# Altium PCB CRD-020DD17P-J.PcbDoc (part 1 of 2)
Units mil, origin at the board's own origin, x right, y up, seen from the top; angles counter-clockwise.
Board outline 2331 x 1574.8 mil, 4 copper layers (TOP, GND02, PWR03, BOTTOM), stack 63 mil thick; 83 components, 45 nets, 202 pads, 150 vias.
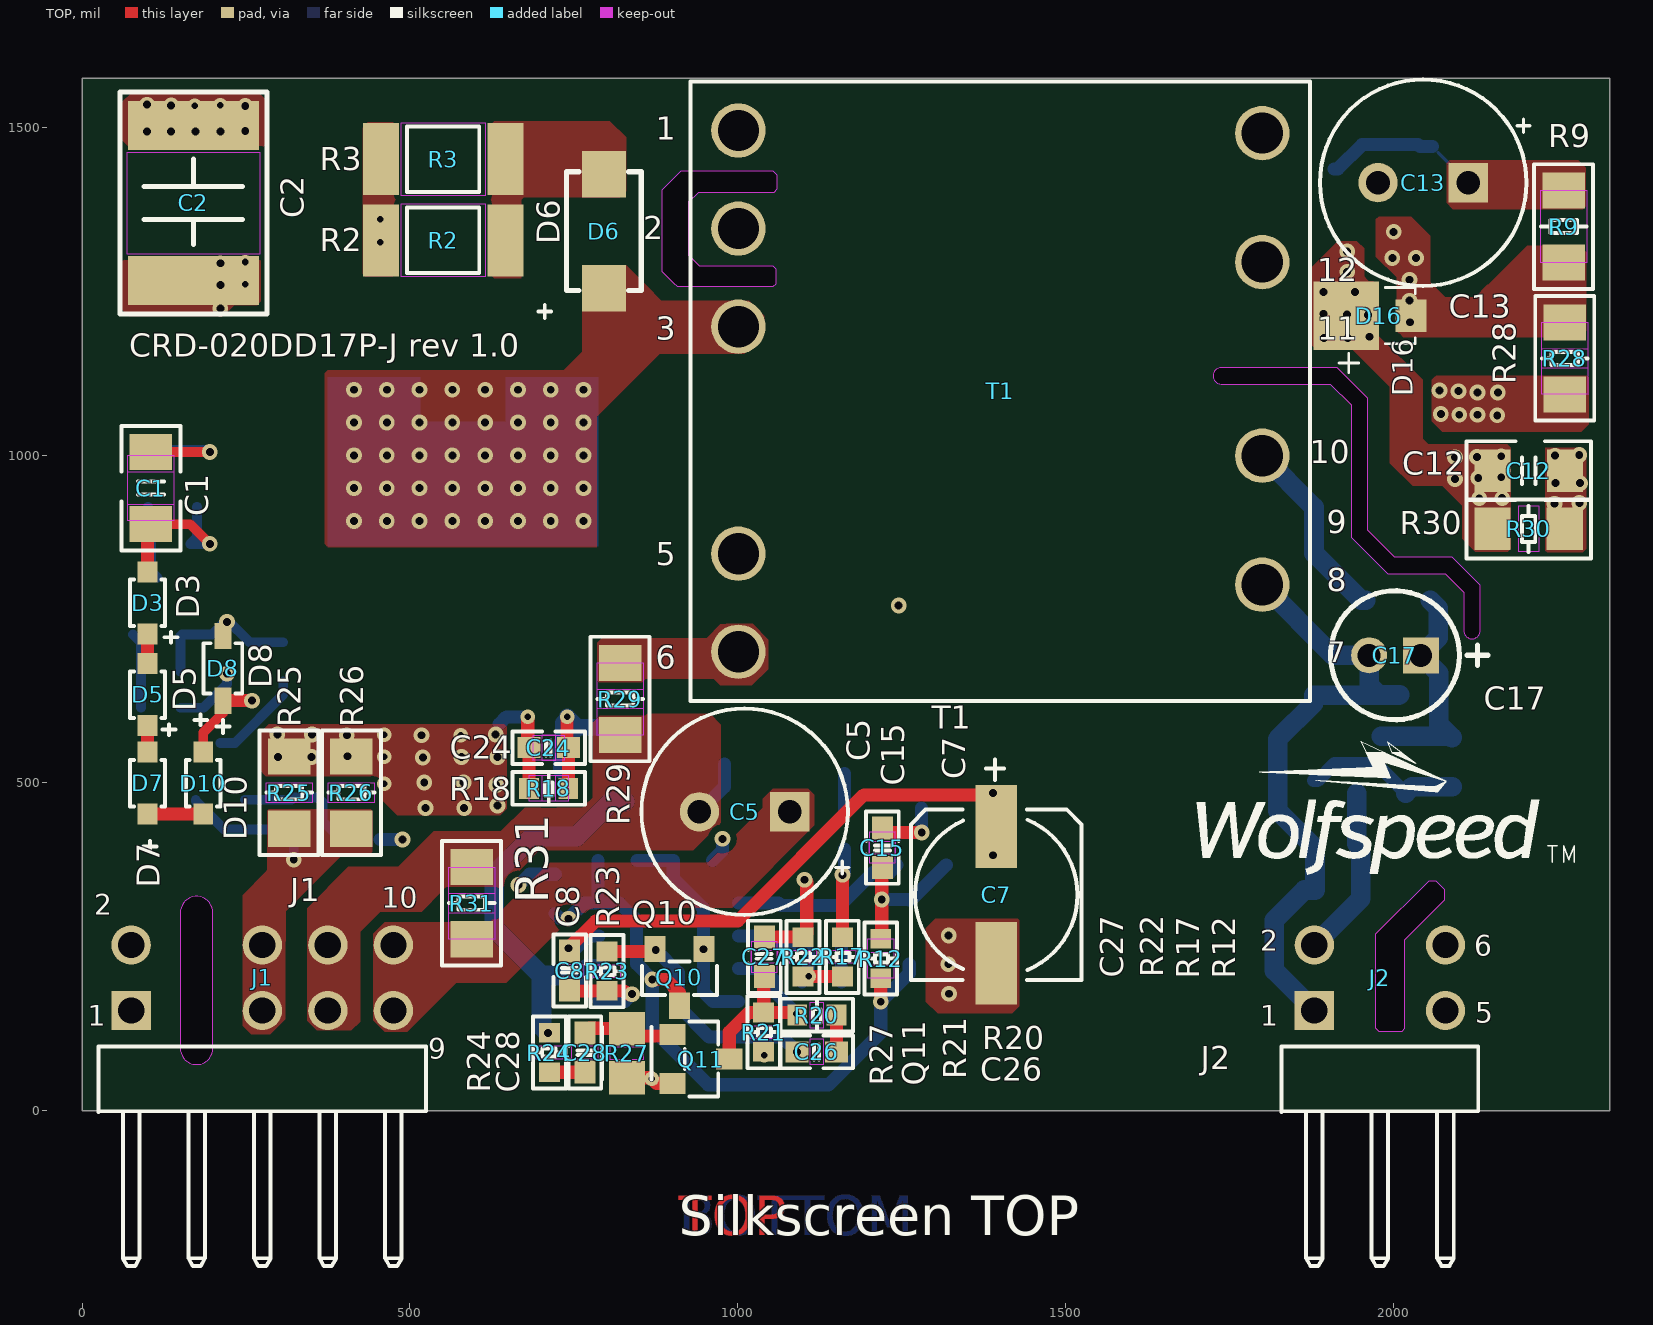
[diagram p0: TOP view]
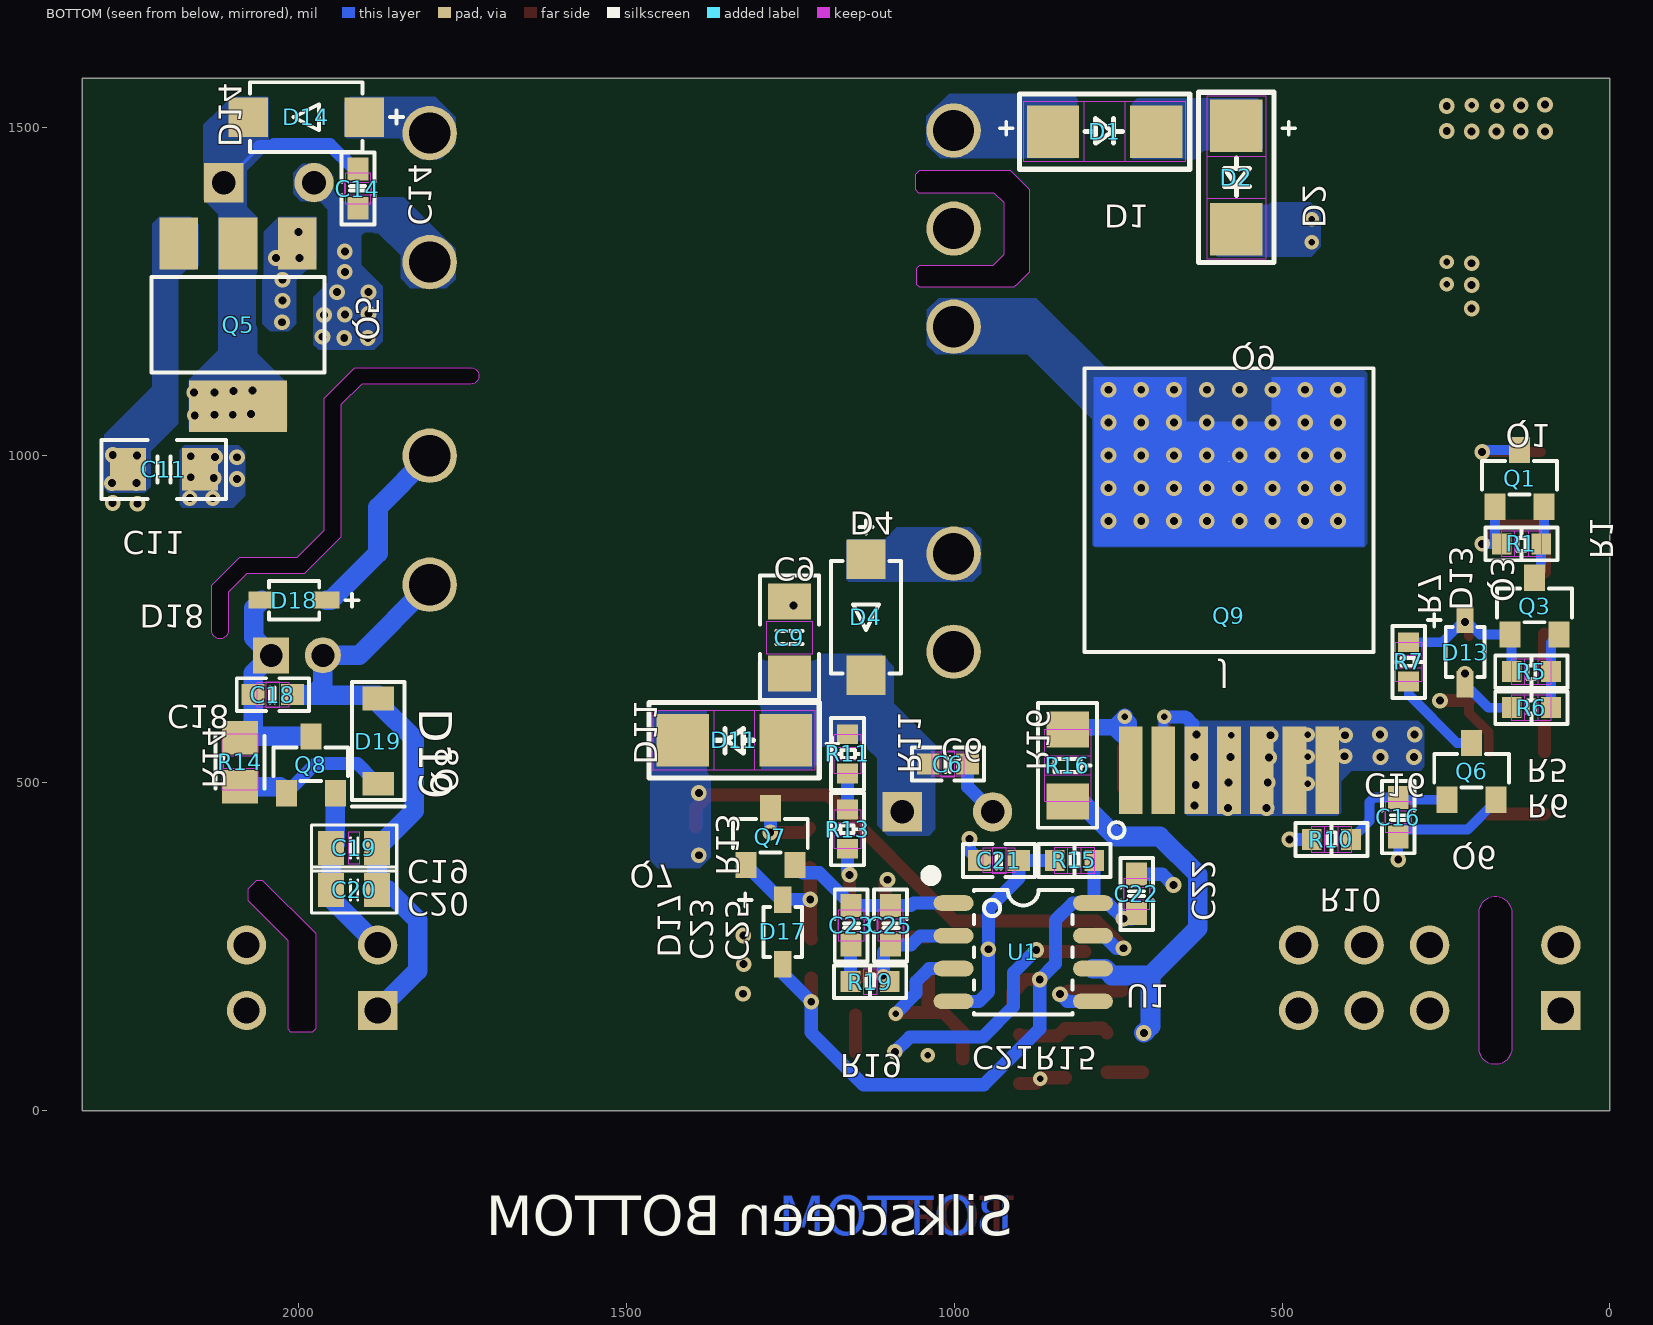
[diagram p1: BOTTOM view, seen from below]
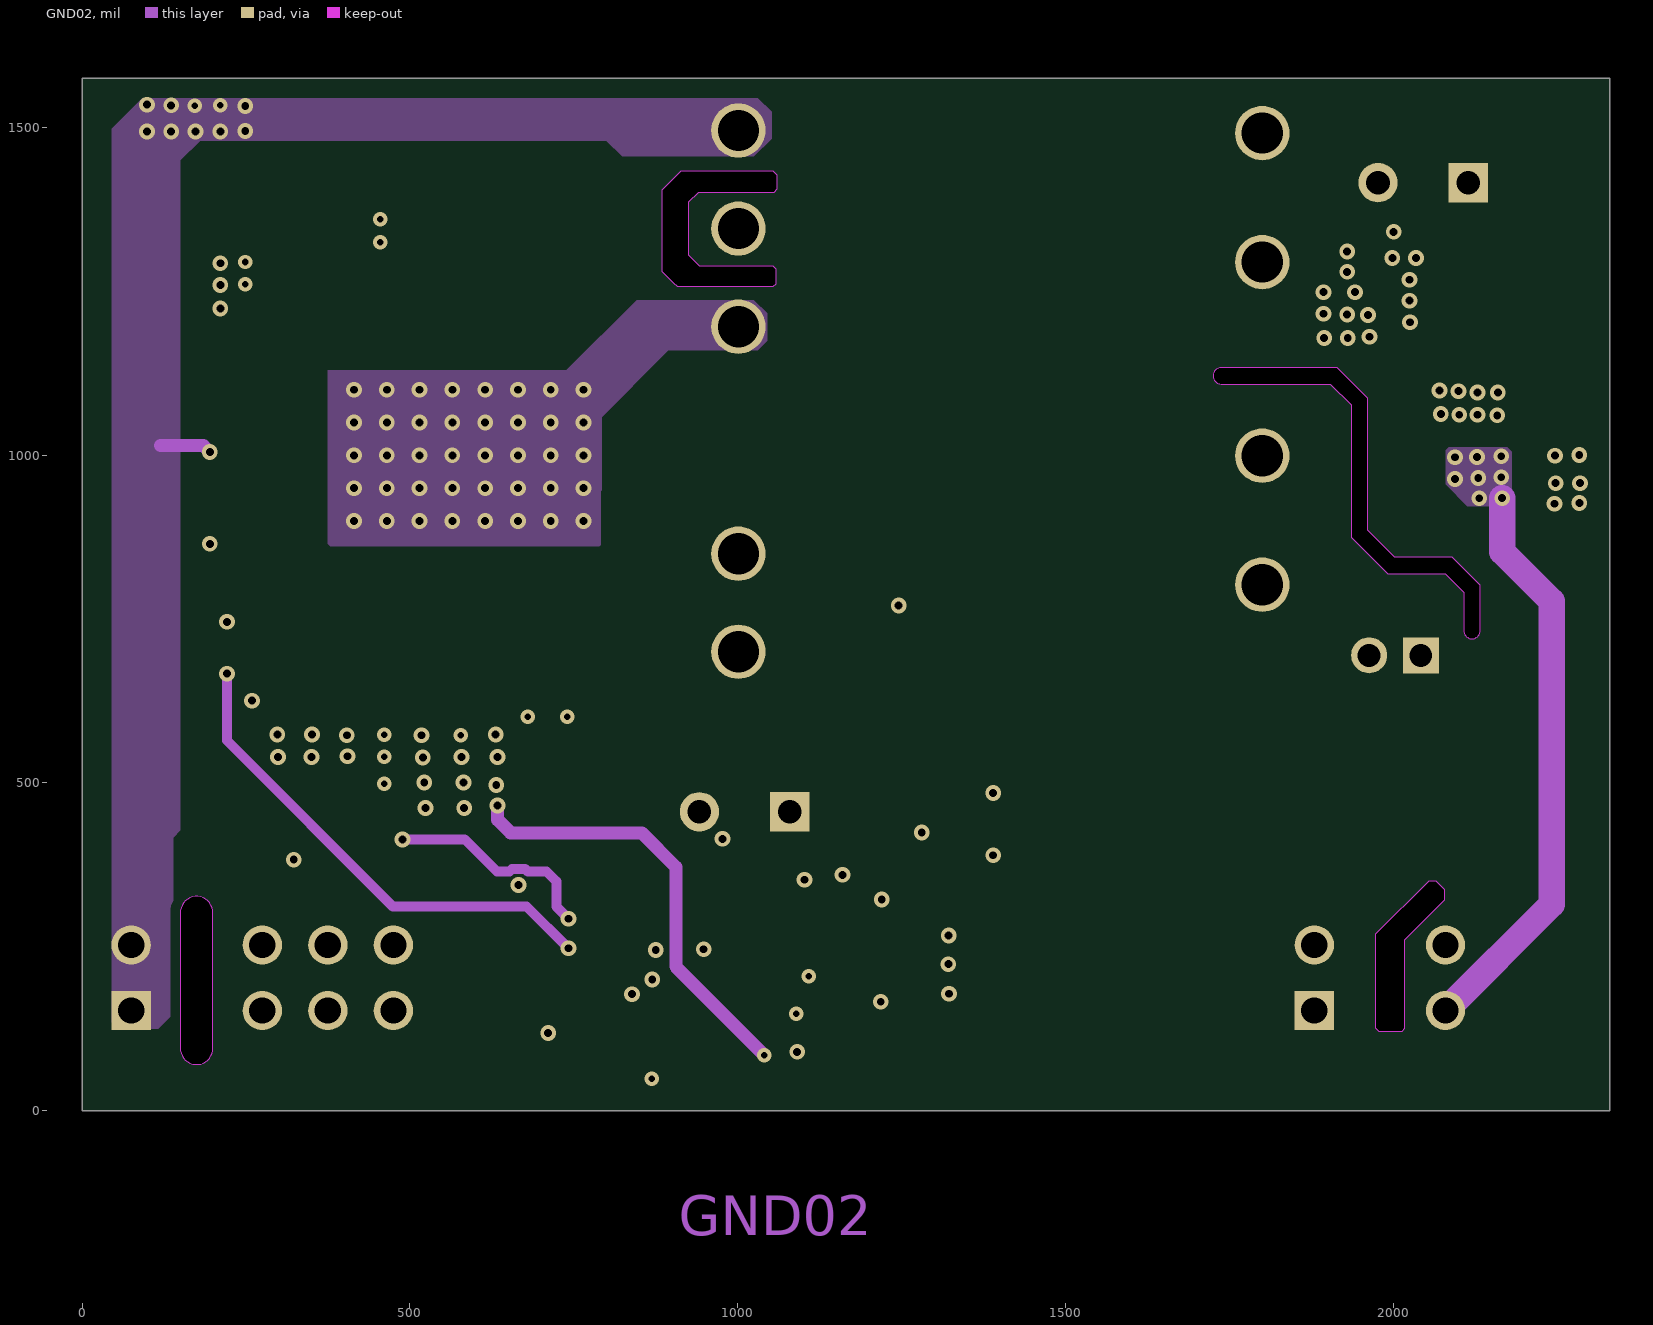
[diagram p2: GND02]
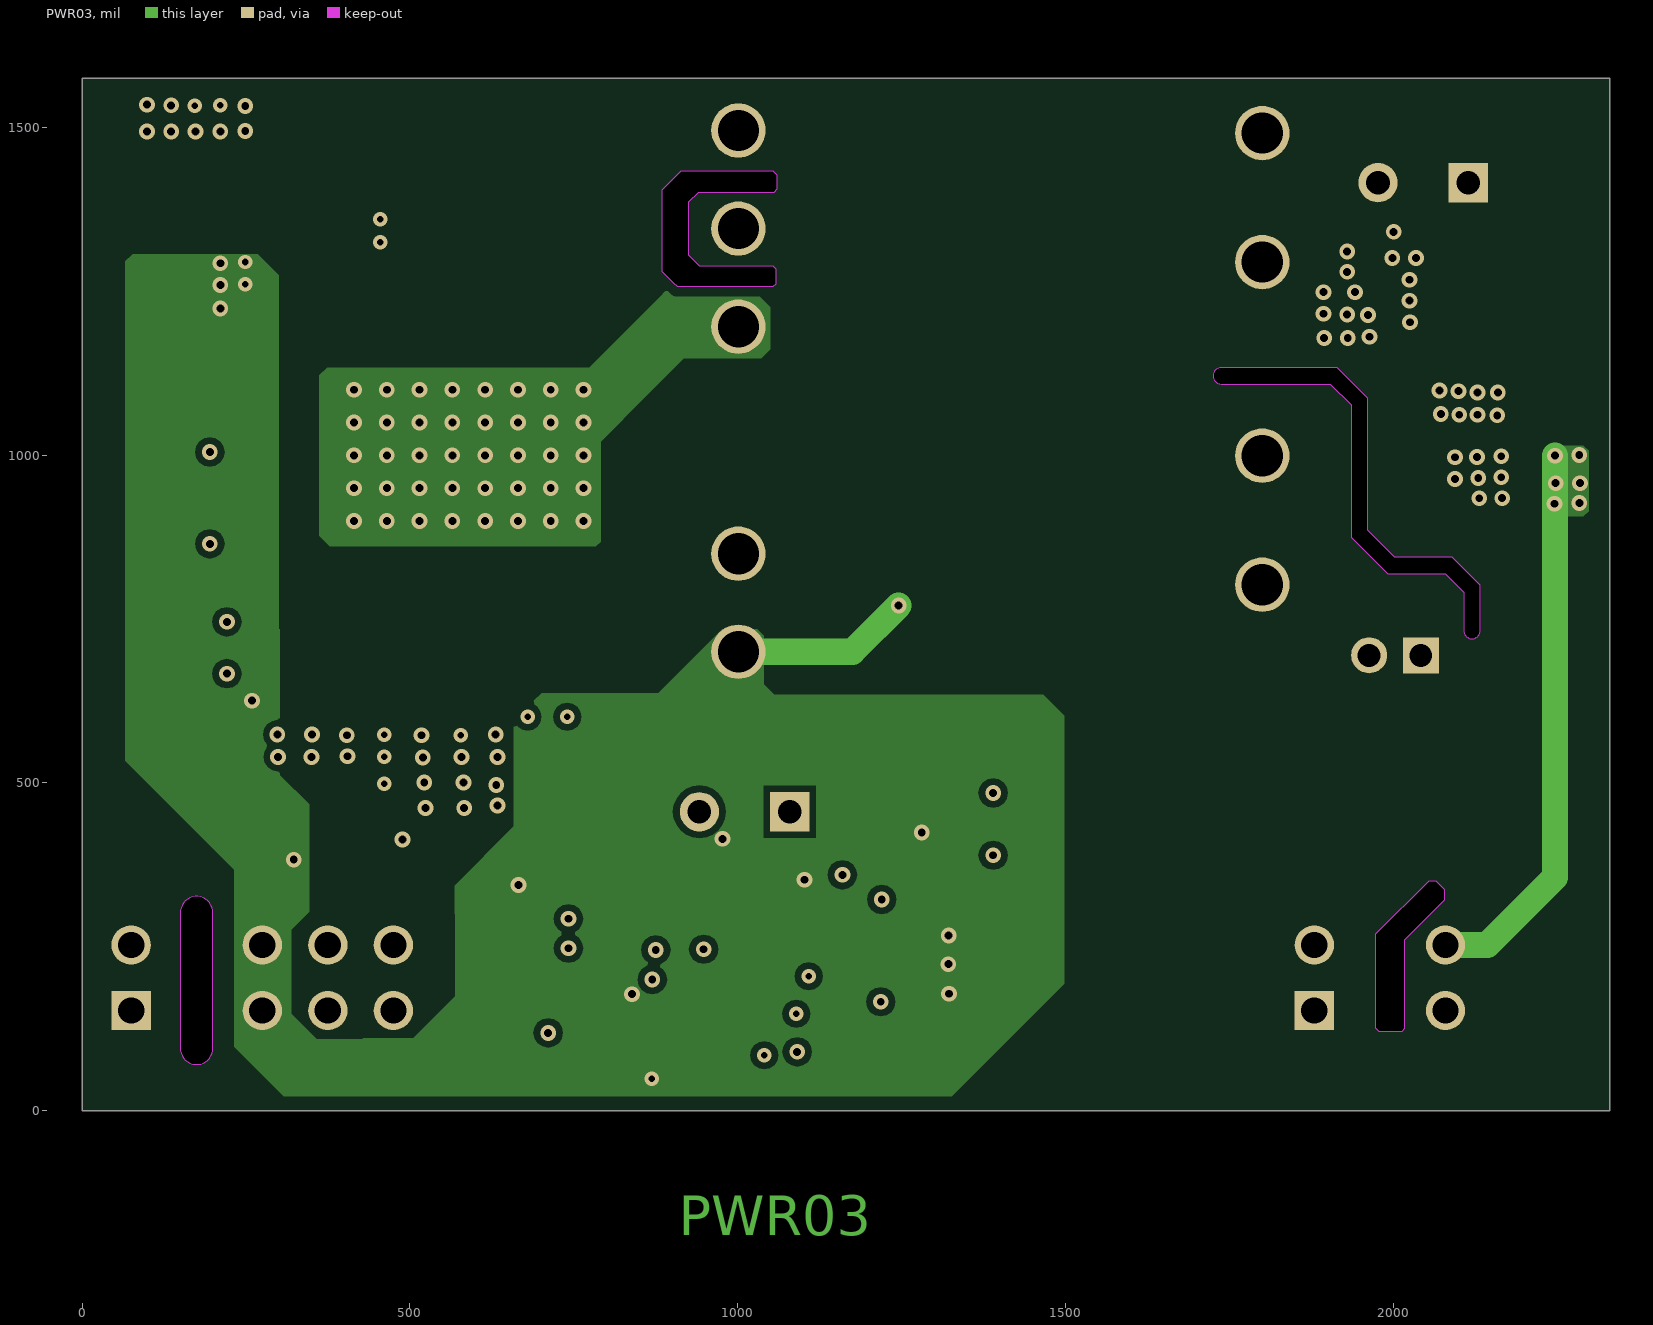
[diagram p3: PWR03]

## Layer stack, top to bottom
Top Solder: solder mask 0.4, Solder Resist, Dk 3.5
TOP: signal copper 1.4
Dielectric 1: core 8.5, FR-4, Dk 4.5
GND02: signal copper 1.2
Dielectric2: core 40.8, FR-4, Dk 4.5
PWR03: signal copper 1.2
Dielectric3: core 8.5, FR-4, Dk 4.5
BOTTOM: signal copper 1.4
Bottom Solder: solder mask 0.4, Solder Resist, Dk 3.5

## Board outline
40,0 0,0 0,1574.8 40,1574.8 2246,1574.8 2331,1574.8 2331,0 2246,0
cut-out: 1737.91,1108.63 1904.29,1108.63 1936.22,1076.71 1936.22,875.2 1992.32,819.09 2079.84,819.09 2108,790.94 2108,732.44 ccw(c2120.5,732.44) 2133,732.44 2133,801.29 2090.2,844.09 2002.68,844.09 1961.22,885.55 1961.22,1087.06 1914.65,1133.63 1737.91,1133.63 ccw(c1737.91,1121.13)
cut-out: 149.74,301.9 149.74,95.45 ccw(c174.74,95.45) 199.74,95.45 199.74,301.9 ccw(c174.74,301.9)
cut-out: 940,1400.8 925,1385.8 925,1319.8 925,1305.8 938,1292.8 942,1288.8 1054,1288.8 1058,1284.8 1058,1264.8 1058,1260.8 1054,1256.8 908.5,1256.8 902.5,1262.3 885,1279.8 885,1404.8 914,1433.8 940,1433.8 1032,1433.8 1054,1433.8 1060,1427.8 1060,1405.8 1055,1400.8 1035,1400.8 1025,1400.8 945,1400.8
cut-out: 2055,350.8 2065,350.8 2078,337.8 2078,320.8 2017,259.8 2017,124.8 2013,120.8 1979,120.8 1974,125.8 1974,269.8

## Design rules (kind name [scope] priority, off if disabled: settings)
BoardOutlineClearance [All] p1: gap=10 ignorepadtopadclearanceinfootprint=FALSE
Clearance [All] p1: gap=5 ignorepadtopadclearanceinfootprint=FALSE
MinimumSolderMaskSliver [All] p1: minsoldermaskwidth=4
PlaneConnect [All] p1: planeconnectstyle=Direct reliefexpansion=20 reliefentries=4 reliefconductorwidth=10 reliefairgap=10
PolygonConnect [All] p1: connectstyle=Direct reliefconductorwidth=10 reliefentries=4 polygonreliefangle="90 Angle" airgapwidth=10
RoutingVias [All] p1: holewidth=28 width=50 viastyle="Through Hole" minholewidth=28 minwidth=50 maxholewidth=28 maxwidth=50
SilkToSilkClearance [All] p1: silktosilkclearance=5
SilkToSolderMaskClearance [IsPad] p1: minsilkscreentomaskgap=5 clearancetoexposedcopper=TRUE
SolderMaskExpansion [All] p1: expansion=4 istentingtop=FALSE
SupplyNets "Schematic Supply Nets_6" [InNet('S_15V')] p1: voltage=0.000
SupplyNets "Schematic Supply Nets_5" [InNet('SGND')] p2: voltage=0.000
SupplyNets "Schematic Supply Nets_4" [InNet('CAN_GND')] p3: voltage=0.000
SupplyNets "Schematic Supply Nets_3" [InNet('CAN+5V')] p4: voltage=0.000
SupplyNets "Schematic Supply Nets_2" [InNet('PGND')] p5: voltage=0.000
SupplyNets "Schematic Supply Nets_1" [InNet('AGND')] p6: voltage=0.000
SupplyNets "Schematic Supply Nets" [InNet('P_15V')] p7: voltage=0.000
Width [All] p1: maxlimit=100 minlimit=5 preferedwidth=8
26 further rules are at their usual default settings.

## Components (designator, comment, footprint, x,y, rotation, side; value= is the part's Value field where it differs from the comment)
C1 "1.5pF" C1206#1 105,949.8 r270 top
C2 "0.22UF" C2220 170,1384.8 r270 top
C5 "APSG250ELL181MH08S" C7C9C13-RNU1E221MDNASQ 1010.78,456.08 r180 top
C6 "1U" C0603#1 1010,528.94 r180 bottom
C7 "35TZV22M6.3X6.1" CAP6_6X6_6 1394.65,329.31 r270 top
C8 "1U" C0603#2 744,213.8 r270 top
C9 "4.7uF" C1206#2 1251.74,721.69 r270 bottom
C11 "10uF" C1206#3 2206.12,978.36 r180 bottom
C12 "10uF" C1206#3 2207.12,976.36 r180 top
C13 "APSG250ELL181MH08S" C7C9C13-RNU1E221MDNASQ 2046,1415.8 r180 top
C14 "1U" C0603#3 1910,1406.8 r90 bottom
C15 "0.33u" 0603#1 1220.96,401.3 r90 top value=0.1uF
C16 "47n" 0603#2 323,447.8 r270 bottom value=0.1uF
C17 "16SEPG150M" C17_16SEPG150M 2003,694.8 r180 top
C18 "1U" C0603#1 2040,634.8 r180 bottom
C19 "10u" C0805#1 1916,400.8 r0 bottom
C20 "10u" C0805#2 1916,336.8 r0 bottom
C21 "1n" C0603#1 932,381.8 r180 bottom
C22 "0.1u" C0603#3 722,330.8 r90 bottom
C23 "22n" 0603#2 1157.62,282.79 r270 bottom value=0.1uF
C24 "1n" C0603#1 712,553.8 r0 top
C25 "100p" C0603#3 1097.62,282.79 r270 bottom
C26 "2.2u" 0603#3 1121,89.8 r0 top
C27 "100p" C0603#1 1041,234.8 r270 top
C28 "22p" C0603#2 767.12,88.74 r90 top
D1 "SMAJ300CA" SMA#1 771,1493.8 r0 bottom
D2 "SMAJ300CA" SMA#2 570,1423.8 r270 bottom
D3 "130V" SOD-323F 100,774.8 r90 top
D4 "SK5150AFL-TP" DO221AC#1 1135,752.8 r90 bottom
D5 "130V" SOD-323F 100,634.8 r90 top
D6 "BYG10YHE3_A/I" DO214AC 796,1341.8 r90 top
D7 "130V" SOD-323F 100,499.8 r90 top
D8 "22V" SOD323#1 215,674.8 r90 top
D10 "130V" SOD-323F 185,499.8 r270 top
D11 "SS16HE3_B/H" SMA#1 1336.11,565.25 r180 bottom
D13 "18V" SOD323#2 221,699.8 r90 bottom
D14 "SK5150AFL-TP" DO221AC#2 1989,1515.8 r0 bottom
D16 "15.6V" DO220AA 1965,1212.8 r0 top
D17 "SD101CWS-HE3-08" SOD323#2 1262.02,272.68 r90 bottom
D18 "BAS100CS_R1_00001" SOD323#1 2007.56,778.82 r0 bottom
D19 "5.6V" SMDSOD123 1879,563.8 r90 bottom
J1 "Connector6" HPR2X4H-254MM-80 275,25.42 r0 top
J2 "Connector6" HPR2X3H-254MM-90 1980,25.42 r0 top
Q1 "TO247-3" SOT23-3 138.01,964.8 r180 bottom
Q3 "TO247-3" SOT23-3 115.01,769.8 r180 bottom
Q5 "PBSS306NZ,135" SOT223 2093,1198.8 r0 bottom
Q6 "" TO236AB 211,517.8 r180 bottom
Q7 "PMBT2907A,235" TO236AB 1280.98,418.27 r180 bottom
Q8 "FMMTL619TA" SOT23-3 1982,527.8 r180 bottom
Q9 "J" D2PAK7L 580.87,915.43 r180 bottom
Q10 "MMBT3904,215" TO-236AB 911.33,203.3 r180 top
Q11 "MMBT3904,215" TO-236AB 944.07,78.82 r270 top
R1 "1M" R0603#1 135,863.8 r0 bottom
R2 "61.9R" R2010 551,1327.8 r0 top
R3 "61.9R" R2010 551,1451.8 r0 top
R5 "1M" R0603#1 120,668.8 r0 bottom
R6 "1k" R0603#1 120,615.8 r180 bottom
R7 "10k" R0603#2 308,684.8 r270 bottom
R9 "510R" R1206#1 2261.43,1348.89 r90 top
R10 "10k" R0603#1 425,414.8 r180 bottom
R11 "0" R0603#2 1162.08,544.43 r90 bottom
R12 "20k" R0603#1 1219.53,232.11 r270 top
R13 "2.49k" R0603#2 1164.08,429.43 r270 bottom
R14 "1k" R0805#1 2090,531.8 r270 bottom
R15 "40.2k" R0603#1 817,382.8 r180 bottom
R16 "10R" 1206 826.49,526.7 r270 bottom
R17 "15k" R0603#3 1161,234.8 r270 top
R18 "10k" R0603#1 712,490.8 r180 top
R19 "324k" R0603#3 1128.62,197.79 r180 bottom
R20 "4.02k" R0603#3 1121,144.8 r180 top
R21 "1k" R0603#3 1041,119.8 r270 top
R22 "3.3k" R0603#3 1101,234.8 r270 top
R23 "15k" R0603#3 802,212.8 r270 top
R24 "2k" R0603#3 712.12,88.74 r90 top
R25 "1.8R" R1206#2 315,485.14 r270 top
R26 "1.8R" R1206#2 410,485.14 r270 top
R27 "127" R0805#2 831.07,87.82 r270 top
R28 "510R" R1206#3 2261.03,1147.81 r270 top
R29 "0" R1206#3 822.03,628.1 r90 top
R30 "50K" R1206#2 2206.99,886.57 r0 top
R31 "50K" R1206#3 593.42,316.6 r270 top
T1 "750345357" XFMRS9_380-2400X2400_750345357 1401,1097.8 r0 top
U1 "UCC28C58QDRQ1" SOIC-8 895,241.8 r180 bottom

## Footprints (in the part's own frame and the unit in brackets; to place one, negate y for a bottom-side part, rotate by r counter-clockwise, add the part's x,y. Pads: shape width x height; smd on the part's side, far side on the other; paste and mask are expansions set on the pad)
0603#1 [mil] "0603"
  rect 35x32 smd: 1(-30,0) 2(30,0)
  TOP keep-out region: -24,-19 -24,19 24,19 24,-19
  TOP keep-out region: -10,-20 -10,20 10,20 10,-20
  silkscreen extent -55,-25 55,25, body extent -55,-25 55,25, height 150
0603#2 [mil] "0603"
  rect 35x32 smd: 1(30,0) 2(-30,0)
  TOP keep-out region: 24,19 24,-19 -24,-19 -24,19
  TOP keep-out region: 10,20 10,-20 -10,-20 -10,20
  silkscreen extent -55,-25 55,25, body extent -55,-25 55,25, height 150
0603#3 [mil] "0603"
  rect 35x32 smd: 1(-30,0) 2(30,0)
  TOP keep-out region: -10,-20 -10,20 10,20 10,-20
  silkscreen extent -55,-25 55,25, body extent -55,-25 55,25, height 150
1206 [mil] "1206"
  rect 55x65 smd: 1(55,-1) 2(-55,-1)
  TOP keep-out region: 15,-36 -15,-36 -15,34 15,34
  TOP keep-out region: 55,-36 -55,-36 -55,34 55,34
  silkscreen extent -95,-46 95,44, body extent -98,-46 98,46, height 150
C7C9C13-RNU1E221MDNASQ [mil] "C7C9C13-RNU1E221MDNASQ"
  rect 60x60 hole 36: 1(-68.9,0)
  round 60 hole 36: 2(68.9,0)
  silkscreen extent -159,-157 157,157, body extent -168,-168 168,168, height 150
C17_16SEPG150M [mil] "C17_16SEPG150M"
  rect 55x55 hole 35: 1(-39.37,0)
  round 55 hole 35: 2(39.37,0)
  silkscreen extent -142,-110 110,110, body extent -99,-99 99,99, height 150
C0603#1 [mil] "C0603"
  rect 35x32 smd: 1(-30,0) 2(30,0)
  TOP keep-out region: -24,-19 -24,19 24,19 24,-19
  TOP keep-out region: -10,-20 -10,20 10,20 10,-20
  silkscreen extent -55,-25 55,25, body extent -55,-25 55,25, height 150
C0603#2 [mil] "C0603"
  rect 35x32 smd: 1(-30,0) 2(30,0)
  TOP keep-out region: -10,-20 -10,20 10,20 10,-20
  silkscreen extent -55,-25 55,25, body extent -55,-25 55,25, height 150
C0603#3 [mil] "C0603"
  rect 35x32 smd: 1(30,0) 2(-30,0)
  TOP keep-out region: 24,19 24,-19 -24,-19 -24,19
  TOP keep-out region: 10,20 10,-20 -10,-20 -10,20
  silkscreen extent -55,-25 55,25, body extent -55,-25 55,25, height 150
C0805#1 [mil] "C0805"
  rect 40x52 smd: 1(-35,0) 2(35,0)
  TOP keep-out region: 8,25 8,-25 -8,-25 -8,25
  silkscreen extent -65,-35 65,35, body extent -65,-35 65,35, height 150
C0805#2 [mil] "C0805"
  rect 40x52 smd: 1(-35,0) 2(35,0)
  silkscreen extent -65,-35 65,35, body extent -65,-35 65,35, height 150
C1206#1 [mil] "C1206"
  rect 55x65 smd: 1(-55,0) 2(55,0)
  TOP keep-out region: -50,-35 -50,35 50,35 50,-35
  TOP keep-out region: -25,-35 -25,35 25,35 25,-35
  silkscreen extent -95,-45 95,45, body extent -95,-45 95,45, height 150
C1206#2 [mil] "C1206"
  rect 55x65 smd: 1(55,0) 2(-55,0)
  TOP keep-out region: 25,35 25,-35 -25,-35 -25,35
  silkscreen extent -95,-45 95,45, body extent -95,-45 95,45, height 150
C1206#3 [mil] "C1206"
  rect 55x65 smd: 1(-55,0) 2(55,0)
  silkscreen extent -95,-45 95,45, body extent -95,-45 95,45, height 150
C2220 [mm] "C2220"
  rect 1.905x5.08 smd: 1(-3,0) 2(3,0)
  TOP keep-out region: -1.95,2.59 -1.95,-2.59 1.96,-2.59 1.96,2.59
  silkscreen extent -4.3,-2.85 4.3,2.85, body extent -2.8,-2.5 2.8,2.5, height 3.81
CAP6_6X6_6 [mil] "CAP6_6X6_6"
  rect 126x63 smd: 1(-104.33,0) 2(104.33,0)
  silkscreen extent -207,-130 130,130, body extent -130,-130 130,130, height 150
D2PAK7L [mil] "D2PAK7L"
  rect 36x134 smd: 1(-150.39,-396.04) 2(-100.39,-396.04) 3(-50.39,-396.04) 4(-0.39,-396.04) 5(49.61,-396.04) 6(99.61,-396.04) 7(149.61,-396.04)
  round 1 smd: 8(-0.39,74.79)
  TOP region: 64.57,203.49 64.57,135.85 -65.35,135.85 -65.35,203.49 -206.69,203.49 -206.69,-53.91 205.91,-53.91 205.91,203.49
  silkscreen extent -221,-499 220,217, body extent -220,-215 220,215, height 150
DO214AC [mil] "DO214AC"
  rect 71x67 smd: 1(-87.21,0) 2(87.21,0)
  silkscreen extent -132,-57 91,100, body extent -126,-58 126,58, height 150
DO220AA [mil] "DO220AA"
  rect 100x105 smd: 1(-36,0)
  rect 47x50 smd: 2(62.5,0)
  silkscreen extent -47,-87 69,43
DO221AC#1 [mil] "DO221AC"
  rect 60x60 smd: 1(88.58,0) 2(-88.58,0)
  silkscreen extent -86,-53 148,53, body extent -122,-54 122,54, height 150
DO221AC#2 [mil] "DO221AC"
  rect 60x60 smd: 1(-88.58,0) 2(88.58,0)
  silkscreen extent -148,-53 86,53, body extent -122,-54 122,54, height 150
HPR2X3H-254MM-90 [mil] "HPR2X3H-254MM-90"
  rect 60x60 hole 40: 1(-100,127.38)
  round 60 hole 40: 2(-100,227.38) 5(100,127.38) 6(100,227.38)
  silkscreen extent -150,-262 150,72
HPR2X4H-254MM-80 [mil] "HPR2X4H-254MM-80"
  rect 60x60 hole 40: 1(-200,127.38)
  round 60 hole 40: 2(-200,227.38) 5(0,127.38) 6(0,227.38) 7(100,127.38) 8(100,227.38) 9(200,127.38) 10(200,227.38)
  silkscreen extent -250,-262 250,72
R0603#1 [mil] "R0603"
  rect 30x32 smd: 1(-30,-1) 2(30,-1)
  TOP keep-out region: -10,19 10,19 10,-21 -10,-21
  TOP keep-out region: -30,19 30,19 30,-21 -30,-21
  silkscreen extent -55,-26 55,24, body extent -56,-26 56,26, height 150
R0603#2 [mil] "R0603"
  rect 30x32 smd: 1(30,1) 2(-30,1)
  TOP keep-out region: 10,-19 -10,-19 -10,21 10,21
  TOP keep-out region: 30,-19 -30,-19 -30,21 30,21
  silkscreen extent -55,-24 55,26, body extent -56,-26 56,26, height 150
R0603#3 [mil] "R0603"
  rect 30x32 smd: 1(-30,-1) 2(30,-1)
  TOP keep-out region: -10,19 10,19 10,-21 -10,-21
  silkscreen extent -55,-26 55,24, body extent -56,-26 56,26, height 150
R0805#1 [mil] "R0805"
  rect 51x55 smd: 1(37.5,0) 2(-37.5,0)
  TOP keep-out region: 42.5,27.5 -42.5,27.5 -42.5,-27.5 42.5,-27.5
  TOP keep-out region: 10,-25 -10,-25 -10,25 10,25
  silkscreen extent -40,-38 40,38, body extent -63,-28 63,28, height 150
R0805#2 [mil] "R0805"
  rect 51x55 smd: 1(-37.5,0) 2(37.5,0)
  TOP keep-out region: -10,25 10,25 10,-25 -10,-25
  silkscreen extent -40,-38 40,38, body extent -63,-28 63,28, height 150
R1206#1 [mil] "R1206"
  rect 55x65 smd: 1(-55,1) 2(55,1)
  TOP keep-out region: -55,36 55,36 55,-34 -55,-34
  silkscreen extent -95,-44 95,46, body extent -98,-46 98,46, height 150
R1206#2 [mil] "R1206"
  rect 55x65 smd: 1(-55,1) 2(55,1)
  TOP keep-out region: -15,36 15,36 15,-34 -15,-34
  silkscreen extent -95,-44 95,46, body extent -98,-46 98,46, height 150
R1206#3 [mil] "R1206"
  rect 55x65 smd: 1(-55,1) 2(55,1)
  TOP keep-out region: -15,36 15,36 15,-34 -15,-34
  TOP keep-out region: -55,36 55,36 55,-34 -55,-34
  silkscreen extent -95,-44 95,46, body extent -98,-46 98,46, height 150
R2010 [mil] "R2010"
  rect 55x110 smd: 1(-95,0) 2(95,0)
  TOP keep-out region: -65,-55 65,-55 65,55 -65,55
  TOP keep-out region: 65,55 -65,55 -65,-55 65,-55
  silkscreen extent -55,-50 55,50, body extent -122,-55 122,55, height 150
SMA#1 [mil] "SMA"
  rect 80x80 smd: 1(78.74,0) 2(-78.74,0)
  TOP keep-out region: -31.5,45.28 -31.5,-45.28 31.5,-45.28 31.5,45.28
  TOP keep-out region: -124.02,45.28 -124.02,-45.28 124.02,-45.28 124.02,45.28
  silkscreen extent -130,-57 160,57, body extent -110,-57 110,57, height 150
SMA#2 [mil] "SMA"
  rect 80x80 smd: 1(-78.74,0) 2(78.74,0)
  TOP keep-out region: 31.5,-45.28 31.5,45.28 -31.5,45.28 -31.5,-45.28
  TOP keep-out region: 124.02,-45.28 124.02,45.28 -124.02,45.28 -124.02,-45.28
  silkscreen extent -130,-57 130,90, body extent -110,-57 110,57, height 150
SMDSOD123 [mil] "SMDSOD123"
  rect 36x48 smd: 1(65,0) 2(-65,0)
  silkscreen extent -100,-40 90,40, body extent -76,-34 76,33, height 56
SOD323#1 [mil] "SOD323"
  rect 40x26 smd: 1(-49.21,0) 2(49.21,0)
  silkscreen extent -98,-30 38,30, body extent -72,-31 72,31, height 150
SOD323#2 [mil] "SOD323"
  rect 40x26 smd: 1(49.21,0) 2(-49.21,0)
  silkscreen extent -38,-30 58,57, body extent -72,-31 72,31, height 150
SOD-323F [mil] "SOD-323F"
  rect 32x30 smd: 1(-47.24,0) 2(47.24,0)
  silkscreen extent -60,-46 35,27, body extent -53,-27 53,27, height 150
SOIC-8 [mil] "SOIC-8"
  oval 61x24 smd: 1(-106.3,75) 2(-106.3,25) 3(-106.3,-25) 4(-106.3,-75) 5(106.3,-75) 6(106.3,-25) 7(106.3,25) 8(106.3,75)
  silkscreen extent -149,-95 75,125, body extent -140,-95 140,95, height 150
SOT23-3 [mil] "SOT23-3"
  rect 32x40 smd: B(-37.39,-43.31) C(0.01,43.31) E(37.42,-43.31)
  silkscreen extent -57,-25 57,27, body extent -58,-66 58,66, height 150
SOT223 [mil] "SOT223"
  rect 59x79 smd: 1(-90.55,-124.02) 2(0,-124.02) 3(90.55,-124.02)
  rect 150x79 smd: 4(0,124.02)
  silkscreen extent -132,-73 132,73, body extent -133,-167 133,167, height 150
TO236AB [mil] "TO236AB"
  rect 32x40 smd: 1(-37.39,-43.31) 2(37.42,-43.31) 3(0.01,43.31)
  silkscreen extent -57,-25 57,27, body extent -58,-66 58,66, height 150
TO-236AB [mil] "TO-236AB"
  rect 32x40 smd: 1(-37.39,-43.31) 2(37.42,-43.31) 3(0.01,43.31)
  silkscreen extent -57,-25 57,27, body extent -58,-66 58,66, height 150
XFMRS9_380-2400X2400_750345357 [mil] "XFMRS9_380-2400X2400_750345357"
  round 83 hole 63: 1(-399.61,397.64) 2(-399.61,248.03) 3(-399.61,98.42) 5(-399.61,-248.03) 6(-399.61,-397.64) 8(399.61,-295.28) 10(399.61,-98.42) 12(399.61,196.85) 14(399.61,393.7)
  silkscreen extent -472,-472 472,472

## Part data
C1: library part "CAP NP_Dup1", "CAP CER 1.5PF 1KV C0G/NP0 1206", Manufacturer="Knowles Syfer"
C2: library part "CAP NP_Dup1", "CAP CER 0.22UF 1.2KV X7R 2220", Manufacturer="Knowles Syfer"
C5 C13: library part "CAP POL", "CAP ALUM POLY 180UF 20% 25V T/H", Manufacturer=UCC
C6 C8 C14 C18: library part "CAP NP", "CAP CER 1UF 25V X7R 0603", Manufacturer=Murata
C7: library part "CAP POL", "CAP ALUM 22UF 20% 35V SMD", Manufacturer=Rubycon
C9: library part "CAP NP_Dup1", "CAP CER 4.7UF 50V X7R 1206", Manufacturer=Yageo
C11 C12: library part "CAP NP_Dup1", "CAP CER 10UF 25V X7R 1206", Manufacturer=Yageo
C15: library part CGA3E2X7R1E104K080AA, "CAP CER 0.33UF 25V X7R 0603", Cap_Case=0603, Manufacturer=Yageo, Supplier Part Number 1=445-5667-1-ND, TempCo=X7R, Tolerance_%=10, Value2=25V, ValueDisplayed=33n
C16: library part CGA3E2X7R1E104K080AA, "CAP CER 0.047UF 50V X7R 0603", Cap_Case=0603, Manufacturer=Yageo, Supplier Part Number 1=445-5667-1-ND, TempCo=X7R, Tolerance_%=10, Value2=25V, ValueDisplayed=33n
C17: library part "CAP POL", "CAP ALUM POLY 150UF 20% 16V T/H", Manufacturer=Panasonic
C19 C20: library part "CAP NP", "CAP CER 10UF 16V X7R 0805", Manufacturer=Yageo
C21 C24: library part "CAP NP_Dup1", "CAP CER 1000PF 25V X7R 0603", Manufacturer=Yageo
C22: library part "CAP NP_Dup1", "CAP CER 0.1UF 50V X7R 0603", Manufacturer=Yageo
C23: library part CGA3E2X7R1E104K080AA, "CAP CER 0.022UF 50V X7R 0603", Cap_Case=0603, Manufacturer=Yageo, Supplier Part Number 1=445-5667-1-ND, TempCo=X7R, Tolerance_%=10, Value2=25V, ValueDisplayed=33n
C25 C27: library part "CAP NP_Dup1", "CAP CER 100PF 25V X7R 0603", Manufacturer=Yageo
C26: library part "CAP NP", "CAP CER 2.2UF 25V X7R 0603", Manufacturer=Murata
C28: library part "CAP NP_Dup1", "CAP CER 22PF 50V C0G/NPO 0603", Manufacturer=Yageo
D1 D2: library part "DIODE ZENER1", "TVS DIODE 300VWM 486VC DO214AC", Manufacturer=Littlefuse
D3 D5 D7 D10: library part "DIODE ZENER1", "DIODE ZENER 130V 200MW UMD2", Manufacturer=Rohm
D4 D14: library part Diode, "DIODE SCHOTTKY 150V 5A DO221AC", Manufacturer=MCC
D6: library part "DIODE ZENER1", "DIODE AVAL 1.6KV 1.5A DO214AC", Manufacturer=Vishay
D8: library part "DIODE ZENER1", "DIODE ZENER 22V 200MW SOD323", Manufacturer=Diode
D11: library part Diode, "DIODE SCHOTTKY 60V 1A DO214AC", Manufacturer=Vishay
D13: library part "DIODE ZENER1", "DIODE ZENER 18V 200MW SOD323", Manufacturer=Diode
D16: library part "DIODE ZENER1", "DIODE ZENER 15.6V 600MW DO220AA", Manufacturer=Vishay
D17: library part Diode, "DIODE SCHOTTKY 40V 30MA SOD323", Manufacturer=Vishay
D18: library part Diode, "DIODE SCHOTTKY 100V 500MA SOD323", Manufacturer=Panjit
D19: library part CMP-004-00036-1, "DIODE ZENER 5.6V 500MW SOD123", Manufacturer=DIODES
J1: library part Connector6_1_2, "CONN HEADER R/A 6POS 2.54MM", Manufacturer="Adam Tech"
J2: library part Connector6_1_1, "CONN HEADER R/A 6POS 2.54MM", Manufacturer="Adam Tech"
Q1 Q3: "MOSFET N-CH 600V 21MA SOT23-3", Manufacturer=Infineon
Q5: library part SOT223, "TRANS NPN 100V 5.1A SOT223", Manufacturer=Nexperia
Q6: library part TO247-3, "MOSFET N-CH 600V 21MA SOT23-3", Manufacturer=Nexperia
Q7: library part SOT23-3_1, "TRANS PNP 60V 0.6A TO236AB", Manufacturer=Nexperia
Q8: library part SOT23-3, "TRANS NPN 50V 1.25A SOT23-3", Manufacturer=DIODES
Q9: "SICFET N-CH 1700V 5.3A D2PAK", Manufacturer=Wolfspeed
Q10 Q11: library part SOT23-3, "TRANS NPN 40V 0.2A TO236AB", Manufacturer=Nexperia
R1 R5: library part R, "RES 1M OHM 1% 1/10W 0603", Manufacturer=Yageo
R2 R3: library part R, "RES SMD 61.9 OHM 1% 3/4W 2010", Manufacturer=Yageo
R6 R21: library part R, "RES SMD 1K OHM 1% 1/10W 0603", Manufacturer=Yageo
R7 R10 R18: library part R, "RES SMD 10K OHM 1% 1/10W 0603", Manufacturer=Yageo
R9 R28: library part R, "RES 510R OHM 5% 1/2W 1206", Manufacturer=Yageo
R11: library part R, "RES SMD 0 OHM 1% 1/10W 0603", Manufacturer=Yageo
R12: library part R, "RES SMD 20K OHM 1% 1/10W 0603", Manufacturer=Yageo
R13: library part R, "RES SMD 2.49K OHM 1% 1/10W 0603", Manufacturer=Yageo
R14: library part R, "RES SMD 1K OHM 1% 1/8W 0805", Manufacturer=Yageo
R15: library part R, "RES SMD 40.2K OHM 1% 1/10W 0603", Manufacturer=Yageo
R16: library part R, "RES 10 OHM 1% 1/4W 1206", Manufacturer=Yageo
R17 R23: library part R, "RES SMD 15K OHM 1% 1/10W 0603", Manufacturer=Yageo
R19: library part R, "RES SMD 324K OHM 1% 1/10W 0603", Manufacturer=Yageo
R20: library part R, "RES SMD 4.02K OHM 1% 1/10W 0603", Manufacturer=Yageo
R22: library part R, "RES SMD 3.3K OHM 1% 1/10W 0603", Manufacturer=Yageo
R24: library part R, "RES SMD 2K OHM 1% 1/10W 0603", Manufacturer=Yageo
R25 R26: library part R, "RES SMD 1.8 OHM 1% 3/4W 1206", Manufacturer=Vishay
R27: library part R, "RES 127 OHM 1% 1/8W 0805", Manufacturer=Yageo
R29: library part R, "RES 0 OHM JUMPER 1/4W 1206", Manufacturer=Yageo
R30 R31: library part R, "RES 50K OHM 5% 1/2W 1206", Manufacturer=Yageo
T1: library part "Trans BB_1_1", "TRANSFORMERS PQ2020 1.6.2mH 115:7:6::6:3", Manufacturer=Wurth
U1: library part UCC28C56H, "INDUSTRIAL, 30-V, LOW-POWER CURR", Manufacturer=TI

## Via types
v1: diameter 24, hole 12, TOP to BOTTOM, 134 vias
v2: diameter 22, hole 10, TOP to BOTTOM, 16 vias

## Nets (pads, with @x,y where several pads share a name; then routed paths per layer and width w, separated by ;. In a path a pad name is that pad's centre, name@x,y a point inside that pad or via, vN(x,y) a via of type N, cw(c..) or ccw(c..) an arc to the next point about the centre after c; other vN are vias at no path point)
AGND: C5.2 C6.2 J1.7 J1.8 R29.1 R31.1 | length 88.7
  BOTTOM w20: C5.2@941.88,456.08 980,494.21 C6.2@980,528.94
CAN+5V: C19.2 C20.2 J2.2 Q8.E | length 263.8
  BOTTOM w30: J2.2@1880,252.8 1951,323.8 C20.2@1951,336.8 C19.2@1951,400.8 1944.58,407.22 Q8.E@1944.58,484.49
CAN_GND: C17.2 C18.2 C19.1 C20.1 D19.1 J2.1 T1.8 | length 1024.6
  BOTTOM w30: T1.8@1800.61,802.53 1908.33,694.8 C17.2@1963.63,694.8 1963.63,649.17 1978,634.8 C18.2@2010,634.8 2008.9,633.7 1879.15,633.7 1879.15,621.95 1824,566.8 1824,457.8 C19.1@1881,400.8 C20.1@1881,336.8 1865,336.8 1819,290.8 1819,213.8 J2.1@1880,152.8
NETC1_1: C1.1 C2.1 D1.1 J1.1 J1.2 Q1.C T1.1 | length 227.5
  TOP w15: C1.1@105,1004.8 v1(195,1004.8)
  GND02 w20: 120,1014.8 185,1014.8 v1(195,1004.8)
  BOTTOM w15: Q1.C@138,1008.11 191.69,1008.11 v1(195,1004.8)
  other v1: 99,1493.8 136,1493.8 173,1493.8 211,1493.8 249,1494.8 249,1532.8 136,1533.8 99,1534.8
  other v2: 172,1532.91 211,1533.8
NETC1_2: C1.2 D3.2 Q1.B R1.2 | length 268.3
  TOP w15: C1.2@105,894.8 165,894.8 v1(195,864.8)
  TOP w20: D3.2@100,822.05 100,889.8 C1.2@105,894.8
  BOTTOM w15: Q1.B@175.4,921.49 175.4,875.21 R1.2@165,864.8 v1(195,864.8)
NETC7_1: C7.1 C8.1 D11.2 D13.2 R6.1 U1.7 | length 1696.9
  TOP w20: v1(742,247.8) 783.6,289.4 1000.29,289.4 1192.69,481.8 1374.65,481.8 1394.65,461.8 C7.1@1394.65,433.64
  GND02 w15: v1(221,666.8) 221,564.8 474,311.8 678,311.8 v1(742,247.8)
  BOTTOM w15: R6.1@150,614.8 185.21,614.8 D13.2@221,650.59 v1(221,666.8)
  BOTTOM w20: v1(742,247.8) 753,247.8 772,266.8 U1.7@788.7,266.8
  other v1: 1390,389.8 1390,484.8
NETC13_1: C13.1 C14.1 D14.2 Q5.2 Q5.4 R9.2 R28.2 | length 231.6
  BOTTOM w5: 2068.9,1461.8 C13.1@2114.9,1415.8
  BOTTOM w20: C14.1@1910,1436.8 1916,1436.8 1953,1473.8 2038.37,1473.8 2041.37,1470.8 2060,1470.8
  other v1: 2159,1060.8 2101,1061.8 2129,1061.8 2073,1062.8 2129,1095.8 2160,1095.8 2100,1097.8 2071,1098.8
NETC15_1: C15.1 D17.1 Q7.1 R12.1 | length 230.9
  TOP w20: R12.1@1218.53,262.11 1220.07,263.65 v1(1220.07,322.33) 1220.07,370.41 C15.1@1220.96,371.3
  BOTTOM w20: v1(1220.07,322.33) D17.1@1261.59,322.33 ; D17.1@1262.02,321.9 D17.1@1261.59,322.33 ; Q7.1@1318.37,374.96 1265.73,322.33 D17.1@1261.59,322.33
NETC16_2: C16.2 Q6.1 R10.2 | length 191.5
  BOTTOM w15: Q6.1@248.39,474.49 319.69,474.49 C16.2@323,477.8 360,477.8 367,470.8 367,441.8 R10.2@395,413.8
NETC17_1: C17.1 C18.1 D18.2 Q8.C R14.2 | length 351.7
  BOTTOM w30: Q8.C@1981.99,571.11 R14.2@2088.19,571.11 ; D18.2@2056.77,778.82 2069.21,766.38 2069.21,721.65 C17.1@2042.37,694.8 2070,667.17 C18.1@2070,634.8 2070,589.3 R14.2@2088.19,571.11 ; R14.2@2090,569.3 R14.2@2088.19,571.11
NETC21_2: C21.2 Q10.1 R15.1 U1.4 | length 334.1
  BOTTOM w20: R15.1@847,381.8 C21.2@902,381.8 902,354.8 948,308.8 948,273.63 948.33,273.3 v1(948.33,246.3) 948.33,219.3 948,218.97 948,181.31 962.51,166.8 U1.4@1001.3,166.8
NETC22_2: C22.2 D17.2 Q10.3 R10.1 R12.2 R15.2 U1.8 | length 1420.6
  TOP w20: v1(870.01,200.16) 891.32,200.16 911.32,180.16 Q10.3@911.32,159.99 ; v1(1218.53,166.3) R12.2@1218.53,202.11
  GND02 w15: v1(489,413.8) 584,413.8 632.83,364.97 652.15,364.97 655.87,368.69 676.17,368.69 679.89,364.97 708.69,364.97 723.69,349.97 723.69,311.11 v1(742,292.8)
  BOTTOM w5: C22.2@722,300.8 734,300.8 v1(742,292.8)
  BOTTOM w20: R10.1@455,413.8 v1(489,413.8) ; C22.2@722,300.8 730,292.8 v1(742,292.8) 766,316.8 U1.8@788.7,316.8 ; R15.2@787,381.8 787,318.5 U1.8@788.7,316.8 ; D17.2@1262.02,223.47 1262.02,209.79 v1(1218.53,166.3) 1218.53,119.12 1139.05,39.64 955.16,39.64 870,124.8 v1(870.01,200.16) 846,224.17 846,290.8 820,316.8 U1.8@788.7,316.8
NETC23_1: C23.1 R19.1 | length 56.4
  BOTTOM w20: C23.1@1157.62,252.79 1158.62,251.79 1158.62,247.25 R19.1@1158.62,196.79
NETC23_2: C23.2 C25.2 Q7.2 U1.1 | length 270.6
  BOTTOM w20: U1.1@1001.3,316.8 1062.61,316.8 1066.62,312.79 C25.2@1097.62,312.79 C23.2@1157.62,312.79 1157.62,314.29 1206.37,363.04 1231.65,363.04 Q7.2@1243.56,374.96
NETC24_1: C24.1 Q9.2 Q9.3 Q9.4 Q9.5 Q9.6 Q9.7 R18.2 R21.2 R25.1 R26.1 | length 906.7
  TOP w20: v2(680,600.8) 680,555.8 C24.1@682,553.8 R18.2@682,491.8
  GND02 w20: v1(634,465.8) 634,443.8 654,423.8 854,423.8 906,371.8 906,219.8 v2(1041,84.8)
  BOTTOM w15: v2(680,600.8) 681.26,599.54 Q9.2@681.26,519.39
  BOTTOM w20: 636.34,589.77 647.37,600.8 v2(680,600.8)
  other v1: 524,461.8 583,461.8 632,496.8 522,500.8 582,500.8 520,538.8 299,539.8 350,539.8 579,539.8 634,539.8 405,540.8 404,572.8 518,572.8 298,573.8 351,573.8 631,573.8
  other v2: 461,498.8 461,539.8 578,572.8 461,573.8
NETC24_2: C24.2 Q9.1 R16.2 R18.1 | length 325.6
  TOP w20: v2(740,600.8) 740,555.8 C24.2@742,553.8 R18.1@742,491.8
  BOTTOM w20: Q9.1@731.26,559.8 731.26,592.06 v2(740,600.8)
  BOTTOM w25: Q9.1@731.26,519.39 731.26,559.8 756.26,584.8 ; v2(740,600.8) 756,584.8 756.26,584.8 ; R16.2@827.49,581.7 824.39,584.8 756.26,584.8
NETC25_1: C25.1 R17.2 R19.2 R22.2 U1.2 | length 219.3
  TOP w20: v2(1108.56,205.03) 1111.64,205.03 1111.87,204.8 R17.2@1160,204.8
  BOTTOM w20: U1.2@1001.3,266.8 1052.61,266.8 1066.62,252.79 C25.1@1097.62,252.79 1108.56,241.85 v2(1108.56,205.03) 1106.86,205.03 R19.2@1098.62,196.79
NETC26_1: C26.1 Q10.2 R23.1 | length 384.8
  TOP w20: R23.1@801,242.8 870.1,242.8 Q10.2@873.91,246.61
  BOTTOM w20: v1(875.33,245.3) 910,210.63 910,159.1 956.76,112.34 1068.46,112.34 v1(1091,89.8)
NETC26_2: C26.2 R20.1 | length 56
  TOP w20: C26.2@1151,89.8 R20.1@1151,145.8
NETC27_2: C27.2 Q11.3 R20.2 R21.1 U1.3 | length 345.5
  TOP w5: R20.2@1087,149.8 1087.76,149.8 v2(1089.85,147.71)
  TOP w20: Q11.3@987.38,78.81 987.38,119.87 1017.31,149.8 R21.1@1040,149.8 ; C27.2@1041,204.8 1040,203.8 R21.1@1040,149.8 ; R20.2@1091,145.8 1087,149.8 R21.1@1040,149.8
  BOTTOM w20: U1.3@1001.3,216.8 1038.67,216.8 1058.67,196.8 1058.67,178.89 v2(1089.85,147.71)
NETC28_1: C28.1 R24.1 | length 54
  TOP w20: R24.1@713.12,58.74 C28.1@767.12,58.74
NETC28_2: C28.2 Q11.1 R27.1 | length 142.2
  TOP w20: C28.2@767.12,118.74 774.18,125.8 788.09,125.8 788.57,125.32 R27.1@831.07,125.32 842.2,114.19 898.74,114.19 Q11.1@900.76,116.21
NETD1_2: D1.2 D2.1
NETD2_2: D2.2 R2.1 R3.1
  other v2: 455,1324.8 455,1359.8
NETD3_1: D3.1 D5.2 | length 45.5
  TOP w20: D5.2@100,682.05 D3.1@100,727.56
NETD4_1: D4.1 T1.5
NETD5_1: D5.1 D7.2 | length 40.5
  TOP w20: D7.2@100,547.05 D5.1@100,587.56
NETD6_1: D6.1 Q9.8 T1.3
  other v1: 415,899.8 465,899.8 515,899.8 565,899.8 615,899.8 665,899.8 715,899.8 765,899.8 415,949.8 465,949.8 515,949.8 565,949.8 615,949.8 665,949.8 715,949.8 765,949.8 415,999.8 465,999.8 515,999.8 565,999.8 615,999.8 665,999.8 715,999.8 765,999.8 415,1049.8 465,1049.8 515,1049.8 565,1049.8 615,1049.8 665,1049.8 715,1049.8 765,1049.8 415,1099.8 465,1099.8 515,1099.8 565,1099.8 615,1099.8 665,1099.8 715,1099.8 765,1099.8
NETD6_2: D6.2 R2.2 R3.2
NETD7_1: D7.1 D10.2 | length 85
  TOP w20: D7.1@100,452.56 D10.2@185,452.56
